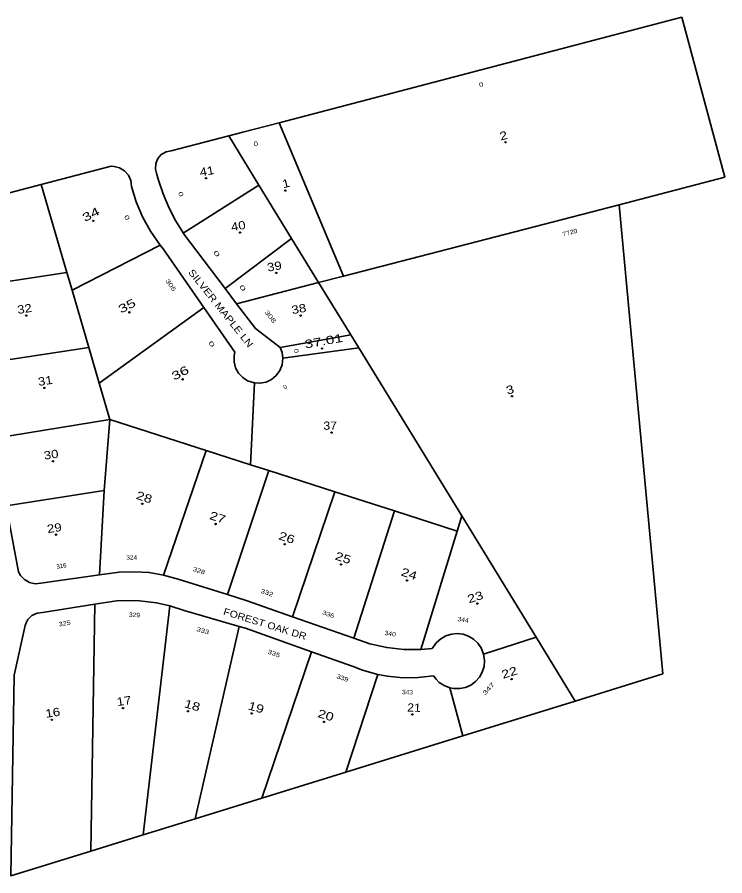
# Model space of a CAD drawing. Extents: x 2546959 to 2550387, y 581906 to 585027.
# Drawn here: x 2549102 to 2550387, y 582686 to 584245 of the extents above; entities that cross this region are included whole.
import ezdxf
from ezdxf.enums import TextEntityAlignment as Align

# ---------------------------------------------------------------- set-up
doc = ezdxf.new("R2010")
doc.units = 0
doc.header["$LTSCALE"] = 5
doc.header["$PDMODE"] = 32
doc.header["$PDSIZE"] = 2.5
for name, color, linetype in [('20', 7, 'Continuous'), ('38', 7, 'Continuous'), ('39', 7, 'Continuous'), ('41', 7, 'Continuous')]:
    doc.layers.add(name, color=color, linetype=linetype)
doc.layers.add('40', color=7, linetype='Continuous', lineweight=35)

msp = doc.modelspace()

# ---------------------------------------------------------------- linework, layer by layer
at = {"layer": '40'}
for p, q in [((2549577.233, 584052.931), (2550308.685, 584244.591)), ((2550308.685, 584244.591), (2550386.687, 583954.249)), ((2549511.602, 584035.734), (2549577.233, 584052.931)), ((2549577.233, 584052.931), (2549694.232, 583774.501)), ((2549381.489, 584002.094), (2549485.616, 584029.016)), ((2549485.616, 584029.016), (2549511.602, 584035.734)), ((2549485.616, 584029.016), (2549540.456, 583939.635)), ((2549145.332, 583940.621), (2549272.401, 583973.833)), ((2550386.687, 583954.249), (2550195.063, 583903.767)), ((2549031.214, 583910.794), (2549145.332, 583940.621)), ((2549145.332, 583940.621), (2549192.015, 583780.951)), ((2549403.085, 583852.376), (2549540.456, 583939.635)), ((2549540.456, 583939.635), (2549599.959, 583842.655)), ((2550195.063, 583903.767), (2549694.232, 583774.501)), ((2550195.063, 583903.767), (2550273.96, 583052.222)), ((2549403.085, 583852.376), (2549402.778, 583852.78)), ((2549479.195, 583751.994), (2549403.085, 583852.376)), ((2549599.959, 583842.655), (2549648.946, 583762.813)), ((2549192.015, 583780.951), (2549019.704, 583754.571)), ((2549192.015, 583780.951), (2549201.357, 583749)), ((2549500.117, 583724.4), (2549648.946, 583762.813)), ((2549440.609, 583717.371), (2549250.655, 583580.386)), ((2549440.609, 583717.371), (2549496.715, 583636.646)), ((2549534.32, 583679.29), (2549500.117, 583724.4)), ((2549579.228, 583644.823), (2549534.32, 583679.29)), ((2549707.304, 583667.698), (2549721.867, 583643.963)), ((2549231.828, 583644.78), (2549039.085, 583615.922)), ((2549584.12, 583625.389), (2549721.867, 583643.963)), ((2549721.867, 583643.963), (2549908.935, 583339.07)), ((2549250.655, 583580.386), (2549270.052, 583514.047)), ((2549532.517, 583580.537), (2549525.145, 583432.101)), ((2549270.052, 583514.047), (2549259.813, 583385.34)), ((2549270.052, 583514.047), (2549444.587, 583457.98)), ((2549366.967, 583231.812), (2549444.587, 583457.98)), ((2549444.587, 583457.98), (2549525.145, 583432.101)), ((2549483.305, 583196.156), (2549558.818, 583421.284)), ((2549525.145, 583432.101), (2549558.818, 583421.284)), ((2549558.818, 583421.284), (2549678.628, 583382.798)), ((2549601.545, 583155.912), (2549678.628, 583382.798)), ((2549678.628, 583382.798), (2549786.52, 583348.139)), ((2549081.302, 583357.597), (2549104.058, 583237.617)), ((2549712.634, 583116.989), (2549786.52, 583348.139)), ((2549786.52, 583348.139), (2549900.478, 583311.531)), ((2549834.4, 583096.347), (2549900.478, 583311.531)), ((2549251.093, 583231.95), (2549278.029, 583235.786)), ((2549144.535, 583216.772), (2549251.093, 583231.95)), ((2549366.967, 583231.812), (2549393.953, 583224.388)), ((2549393.953, 583224.388), (2549483.305, 583196.156)), ((2549483.305, 583196.156), (2549517.683, 583185.295)), ((2549147.609, 583163.999), (2549242.58, 583178.769)), ((2549242.58, 583178.769), (2549282.074, 583184.911)), ((2549379.012, 583175.725), (2549405.098, 583167.535)), ((2549517.683, 583185.295), (2549601.545, 583155.912)), ((2549405.098, 583167.535), (2549504.655, 583138.594)), ((2549601.545, 583155.912), (2549712.634, 583116.989)), ((2549504.655, 583138.594), (2549424.797, 582789.354)), ((2549504.655, 583138.594), (2549516.438, 583135.169)), ((2549636.195, 583092.456), (2549516.438, 583135.169)), ((2549712.634, 583116.989), (2549712.837, 583116.919)), ((2549834.4, 583096.347), (2549855.37, 583098.124)), ((2549711.442, 583065.619), (2549636.195, 583092.456)), ((2549886.988, 583027), (2549910.993, 582939.862)), ((2549910.993, 582939.862), (2550115.103, 583003.046)), ((2549424.797, 582789.354), (2549546.008, 582826.877))]:
    msp.add_line(p, q, dxfattribs=at)
for points in [[(2549354.267, 583961.416), (2549352.521, 583968.881), (2549353.127, 583978.703), (2549356.862, 583987.805), (2549363.331, 583995.22), (2549371.841, 584000.159), (2549381.489, 584002.094)], [(2549272.401, 583973.833), (2549277.401, 583973.703), (2549287.448, 583971.196), (2549296.532, 583965.692), (2549303.552, 583957.723), (2549307.868, 583948.018), (2549309.082, 583937.467)], [(2549402.778, 583852.78), (2549389.066, 583875.507), (2549376.982, 583899.141), (2549366.585, 583923.565), (2549357.929, 583948.657), (2549354.267, 583961.416)], [(2549309.082, 583937.467), (2549317.723, 583909.123), (2549329.25, 583881.825), (2549343.541, 583855.866), (2549361.129, 583830.668)], [(2549500.117, 583724.4), (2549479.195, 583751.994), (2549599.959, 583842.655)], [(2549361.129, 583830.668), (2549201.357, 583749), (2549231.828, 583644.78), (2549250.655, 583580.386)], [(2549361.129, 583830.668), (2549366.624, 583823.818), (2549440.609, 583717.371)], [(2549694.232, 583774.501), (2549648.946, 583762.813), (2549707.304, 583667.698)], [(2549584.12, 583625.389), (2549582.69, 583635.787), (2549579.228, 583644.823), (2549707.304, 583667.698)], [(2549496.715, 583636.646), (2549495.378, 583630.061), (2549495.388, 583618.881), (2549498.182, 583608.055), (2549503.582, 583598.266), (2549511.25, 583590.13), (2549520.061, 583584.478)], [(2549532.517, 583580.537), (2549542.502, 583580.054), (2549553.477, 583582.18), (2549563.579, 583586.97), (2549572.17, 583594.125), (2549578.709, 583603.194), (2549582.784, 583613.604), (2549584.12, 583625.389)], [(2549520.061, 583584.478), (2549521.728, 583583.784), (2549532.517, 583580.537)], [(2549270.052, 583514.047), (2549058.121, 583479.818), (2549081.302, 583357.597), (2549259.719, 583385.325)], [(2549251.093, 583231.95), (2549259.719, 583385.325), (2549259.813, 583385.34)], [(2549900.478, 583311.531), (2549908.935, 583339.07), (2550044.053, 583118.847)], [(2549144.535, 583216.772), (2549134.2, 583216.029), (2549124.089, 583218.291), (2549115.056, 583223.368), (2549107.867, 583230.83), (2549104.058, 583237.617)], [(2549278.029, 583235.786), (2549287.01, 583236.77), (2549314.084, 583237.857), (2549341.125, 583236.138), (2549366.967, 583231.812)], [(2549242.58, 583178.769), (2549235.186, 582730.658), (2549330.628, 582760.203)], [(2549282.074, 583184.911), (2549292.489, 583185.472), (2549323.766, 583184.946), (2549354.811, 583181.119), (2549379.012, 583175.725)], [(2549379.012, 583175.725), (2549330.628, 582760.203), (2549424.797, 582789.354)], [(2549115.828, 583139.833), (2549117.703, 583145.177), (2549121.147, 583151.03), (2549128.416, 583158.133), (2549137.542, 583162.606), (2549147.609, 583163.999)], [(2549095.962, 583049.736), (2549095.984, 583049.839), (2549115.828, 583139.833)], [(2549855.37, 583098.124), (2549856.9, 583100.624), (2549862.891, 583109.061), (2549870.816, 583116.146), (2549880.055, 583121.402), (2549890.194, 583124.594), (2549900.778, 583125.578), (2549911.332, 583124.31), (2549921.381, 583120.846), (2549930.476, 583115.342), (2549938.206, 583108.047), (2549944.226, 583099.286), (2549948.656, 583087.965)], [(2549712.837, 583116.919), (2549742.285, 583106.85), (2549772.648, 583100.02), (2549803.571, 583096.508), (2549834.4, 583096.347)], [(2549948.656, 583087.965), (2550044.053, 583118.847), (2550115.103, 583003.046), (2550273.96, 583052.222)], [(2549636.195, 583092.456), (2549546.008, 582826.877), (2549698.481, 582874.077)], [(2549948.656, 583087.965), (2549950.26, 583076.33), (2549949.326, 583065.742), (2549946.183, 583055.587), (2549940.971, 583046.323), (2549933.923, 583038.366), (2549925.358, 583032.072), (2549915.658, 583027.723), (2549905.259, 583025.517), (2549894.63, 583025.55), (2549886.988, 583027)], [(2549756.789, 583051.174), (2549728.855, 583058.979), (2549711.442, 583065.619)], [(2549095.984, 583049.839), (2549089.777, 582685.644), (2549235.186, 582730.658)], [(2549756.789, 583051.174), (2549698.481, 582874.077), (2549910.993, 582939.862)], [(2549857.579, 583048.8), (2549829.825, 583045.53), (2549801.88, 583045.244), (2549774.065, 583047.943), (2549756.789, 583051.174)], [(2549886.988, 583027), (2549876.901, 583030.938), (2549868.05, 583036.825), (2549862.337, 583042.395), (2549857.579, 583048.8)]]:
    msp.add_lwpolyline(points, dxfattribs=at)
at = {"layer": '41'}
for p in [(2549988.343, 584017.587), (2549444.511, 583952.085), (2549588.333, 583929.648), (2549239.781, 583874.828), (2549506.316, 583853.583), (2549571.984, 583780.189), (2549118.102, 583702.931), (2549305.449, 583708.726), (2549616.406, 583702.932), (2549655.034, 583643.058), (2549402.019, 583587.047), (2549150.936, 583571.594), (2550000.138, 583556.447), (2549672.416, 583490.476), (2549166.387, 583438.327), (2549328.625, 583361.07), (2549461.892, 583324.373), (2549172.181, 583305.058), (2549587.433, 583287.677), (2549689.798, 583250.98), (2549809.546, 583222.009), (2549937.339, 583179.935), (2549999.297, 583042.927), (2549293.859, 582990.237), (2549411.674, 582984.443), (2549164.454, 582968.991), (2549527.559, 582980.58), (2549819.202, 582978.649), (2549658.895, 582965.129)]:
    msp.add_point(p, dxfattribs=at)

# ---------------------------------------------------------------- texts
at = {"layer": '20'}
for s, rotation, width, p in [('SILVER MAPLE LN', 308.787, 1.2, (2549466.461, 583712.299)), ('FOREST OAK DR', 342.806, 1.15, (2549549.837, 583137.059))]:
    msp.add_text(s, height=12.5, rotation=rotation, dxfattribs=dict(at, width=width)).set_placement(p, align=Align.CENTER)
at = {"layer": '38'}
for s, rotation, width, p in [('2', 14.683, 1.25, (2549986.595, 584022.288)), ('41', 10.127, 1.2, (2549447.399, 583957.683)), ('1', 14.683, 1.25, (2549591.4, 583935.546)), ('34', 27.074, 1.45, (2549238.674, 583879.825)), ('40', 10.127, 1.2, (2549504.328, 583858.251)), ('39', 10.127, 1.2, (2549569.98, 583784.865)), ('35', 27.074, 1.45, (2549304.38, 583713.747)), ('32', 8.834, 1.2, (2549116.043, 583707.715)), ('38', 10.127, 1.2, (2549614.406, 583707.64)), ('37.01', 10.127, 1.4, (2549659.554, 583649.209)), ('36', 27.074, 1.45, (2549400.912, 583592.041)), ('31', 8.834, 1.2, (2549153.745, 583577.065)), ('3', 14.683, 1.25, (2549998.38, 583561.066)), ('30', 8.834, 1.2, (2549164.308, 583443.078)), ('28', 342.191, 1.3, (2549330.092, 583365.92)), ('27', 342.191, 1.3, (2549463.37, 583329.228)), ('29', 8.834, 1.2, (2549170.121, 583309.852)), ('26', 342.191, 1.3, (2549588.915, 583292.535)), ('25', 342.191, 1.3, (2549691.26, 583255.842)), ('24', 342.191, 1.3, (2549811.044, 583226.829)), ('23', 17.938, 1.3, (2549935.77, 583184.664)), ('22', 17.938, 1.3, (2549997.742, 583047.599)), ('17', 8.84, 1.2, (2549296.676, 582995.739)), ('18', 343.791, 1.3, (2549417.499, 582988.006)), ('19', 343.791, 1.3, (2549533.391, 582984.167)), ('16', 8.84, 1.2, (2549167.29, 582974.512)), ('20', 343.791, 1.3, (2549659.985, 582970.086)), ('21', 358.37, 1.1, (2549822.071, 582983.604))]:
    msp.add_text(s, height=15, rotation=rotation, dxfattribs=dict(at, width=width)).set_placement(p, align=Align.CENTER)
at = {"layer": '38', "width": 1.1}
msp.add_text('37', height=15, dxfattribs=at).set_placement((2549669.936, 583495.476), align=Align.CENTER)
at = {"layer": '39'}
for s, rotation, width, p in [('0', 14.683, 1.3, (2549945.247, 584118.336)), ('0', 14.683, 1.3, (2549535.92, 584011.03)), ('0', 292.053, 1.5, (2549395.267, 583921.902)), ('0', 292.895, 1.5, (2549297.375, 583879.255)), ('7720', 14.472, 1.15, (2550106.335, 583849.848)), ('0', 307.17, 1.95, (2549460.645, 583812.788)), ('305', 304.801, 1.4, (2549377.37, 583755.776)), ('0', 307.169, 1.95, (2549507.897, 583750.496)), ('308', 307.17, 1.45, (2549558.353, 583698.554)), ('0', 304.801, 1.85, (2549451.554, 583649.004)), ('0', 283.215, 1.25, (2549604.771, 583637.874)), ('324', 0.317, 1.1, (2549309.565, 583259.706)), ('316', 8.106, 0.95, (2549182.413, 583244.449)), ('328', 342.466, 1.25, (2549430.585, 583235.832)), ('332', 340.691, 1.3, (2549553.997, 583195.896)), ('329', 357.015, 1.15, (2549314.374, 583155.489)), ('336', 340.691, 1.25, (2549665.354, 583156.857)), ('344', 351.629, 1.15, (2549910.95, 583146.705)), ('325', 8.84, 1.2, (2549188.244, 583140.063)), ('333', 343.791, 1.3, (2549437.731, 583126.849)), ('340', 351.453, 1.15, (2549778.419, 583121.424)), ('335', 340.371, 1.3, (2549566.529, 583085.489)), ('339', 340.371, 1.25, (2549691.006, 583041.116)), ('347', 46.953, 1.45, (2549960.476, 583022.538)), ('343', 358.545, 1.1, (2549810.258, 583015.122))]:
    msp.add_text(s, height=8, rotation=rotation, dxfattribs=dict(at, width=width)).set_placement(p, align=Align.CENTER)
msp.add_text('0', height=8, rotation=42.681, dxfattribs=at).set_placement((2549590.857, 583570.423), align=Align.CENTER)

doc.saveas('drawing.dxf')
